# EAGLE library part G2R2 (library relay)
RELAY 2 x switch, Omron
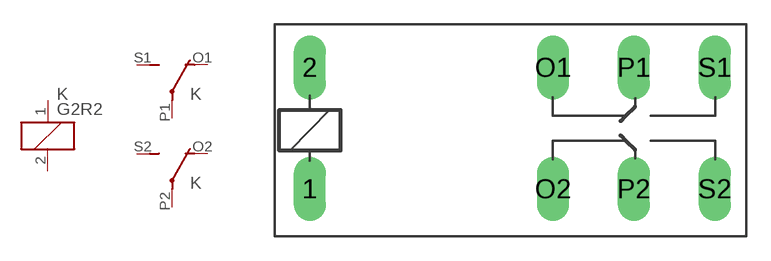
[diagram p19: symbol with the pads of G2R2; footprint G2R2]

Designator prefix K; gates 1=K 2=U 3=U

## G2R2 (MF: OMRON COMPONENTS USA; MPN: G2R-2-DC6; OC_FARNELL: unknown; OC_NEWARK: 89C5317)  [G2R2]
1  1:1  pas
2  1:2  pas
O1  2:O  pas
O2  3:O  pas
P1  2:P  pas
P2  3:P  pas
S1  2:S  pas
S2  3:S  pas

## Footprint G2R2 (pad centres in mm)
RELAY 2 x switch, Omron
drill 1.321 long: 1 -2.54,-3.683; 2 -2.54,3.81; O1 12.471,3.81; O2 12.471,-3.683; P1 17.45,3.81; P2 17.45,-3.683; S1 22.454,3.81; S2 22.454,-3.683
